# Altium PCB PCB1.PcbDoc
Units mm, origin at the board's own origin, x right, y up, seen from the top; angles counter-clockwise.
Board outline 64.13 x 24.77 mm, 2 copper layers (Top Layer, Bottom Layer); 42 components, 34 nets, 201 pads, 2 vias.
Unrouted connection lines stored in the file: 120.
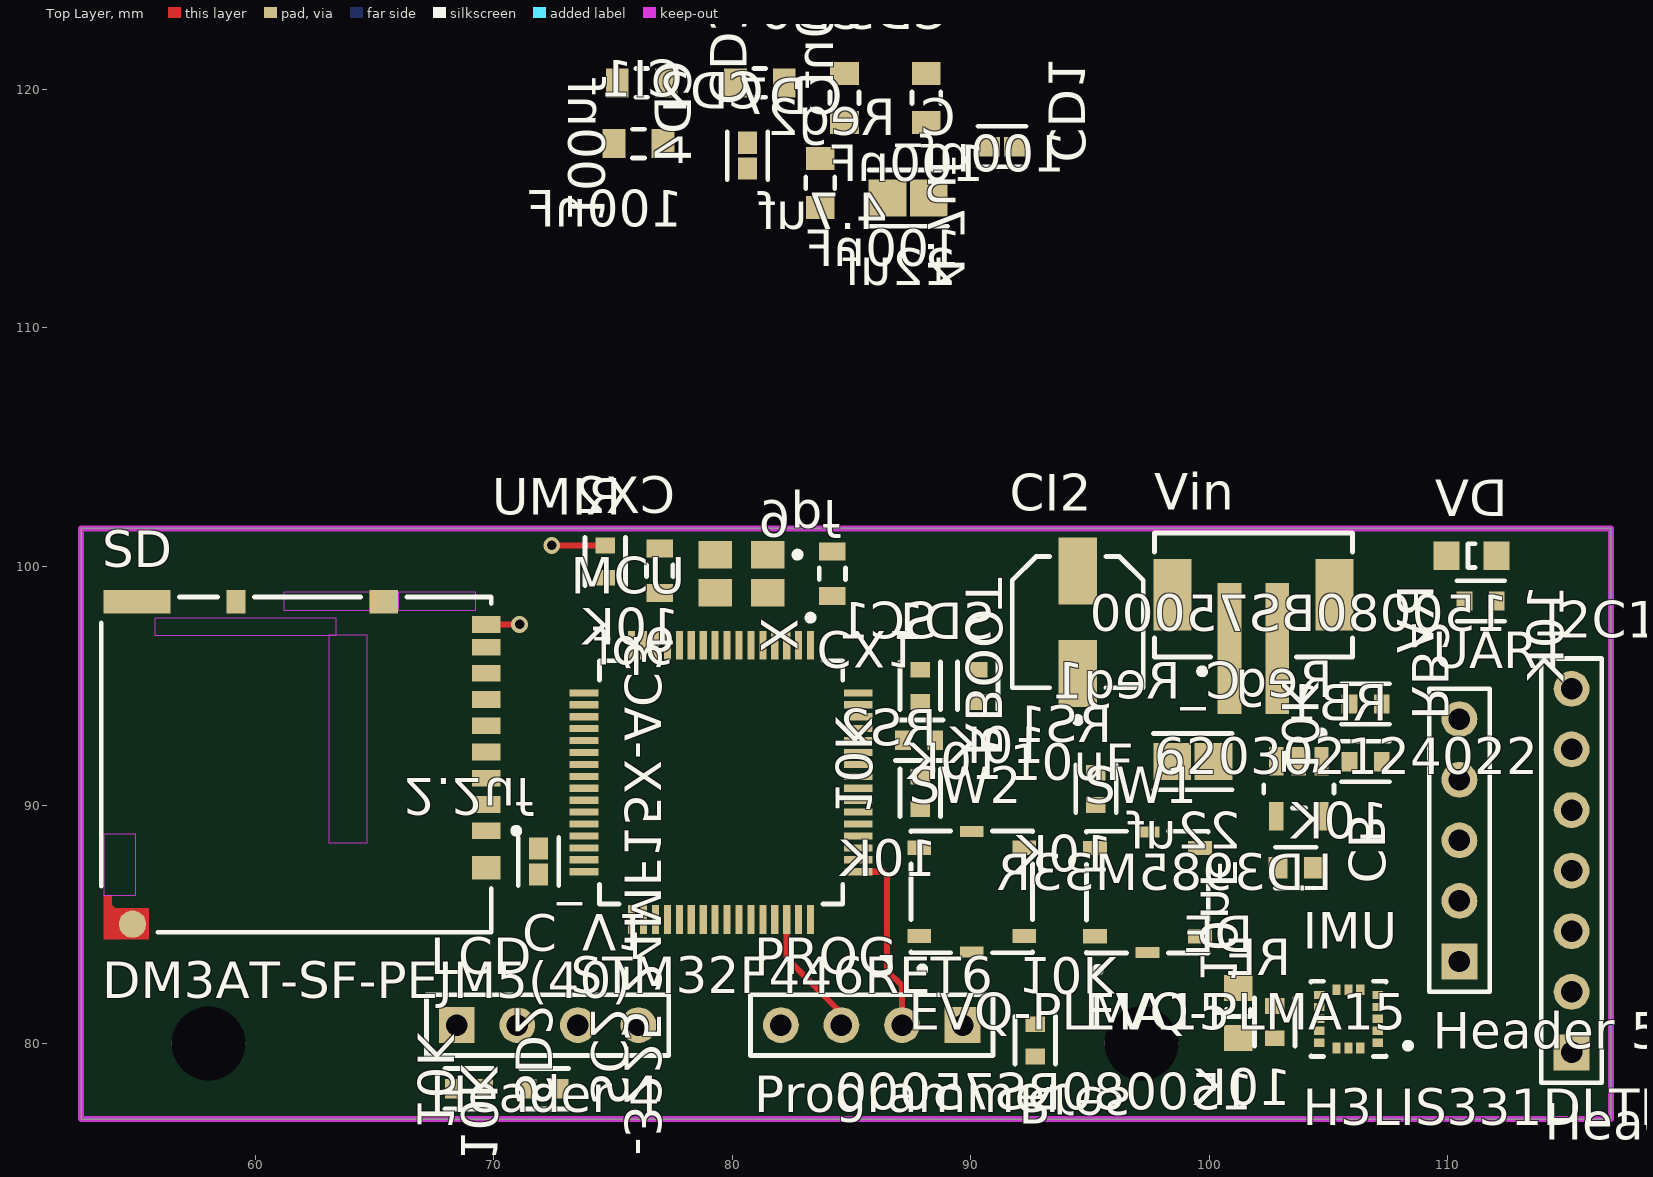
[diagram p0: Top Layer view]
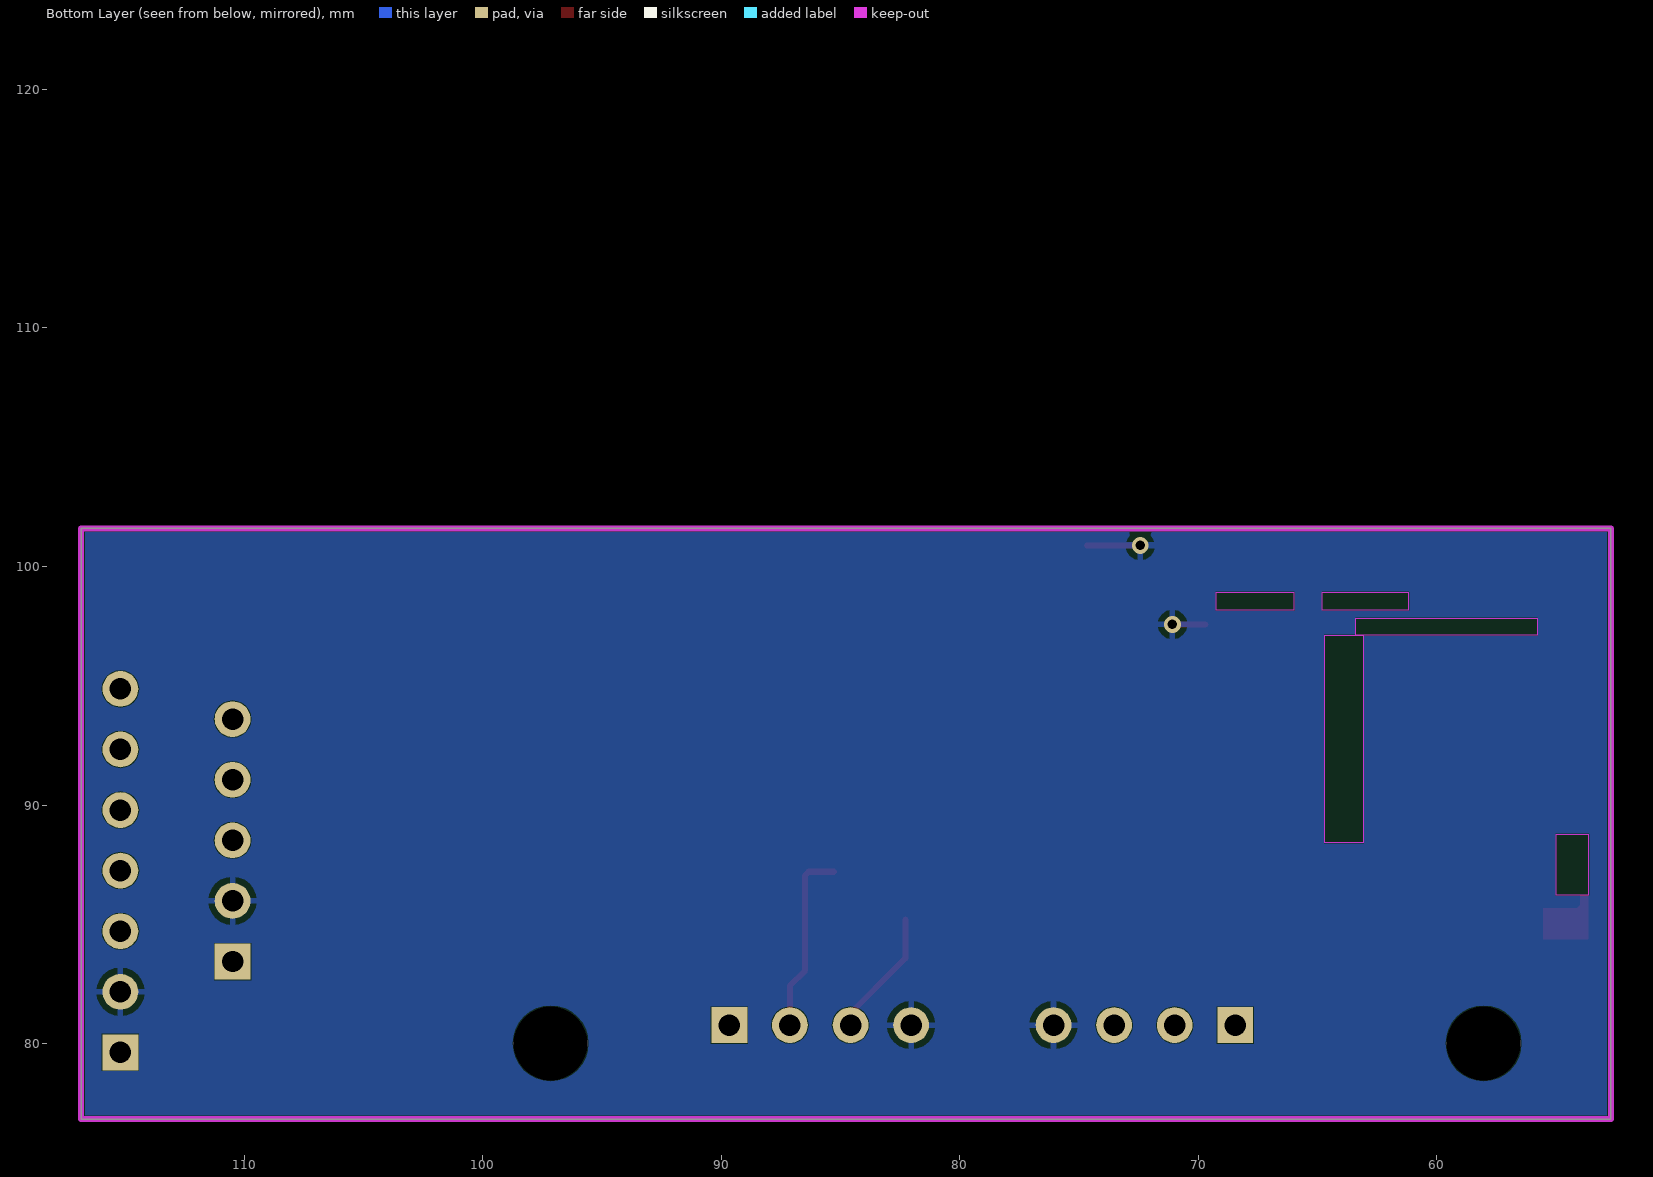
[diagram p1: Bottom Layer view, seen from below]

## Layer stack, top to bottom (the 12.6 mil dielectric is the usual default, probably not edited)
Top Solder: solder mask 0.0102, Solder Resist, Dk 3.5
Top Layer: signal copper 0.0356
Dielectric 1: dielectric 0.32, FR-4, Dk 4.8
Bottom Layer: signal copper 0.0356
Bottom Solder: solder mask 0.0102, Solder Resist, Dk 3.5

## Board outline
52.705,76.835 52.705,101.6 116.84,101.6 116.84,76.835

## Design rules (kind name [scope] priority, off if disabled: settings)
Clearance [All] p1: gap=0.025 ignorepadtopadclearanceinfootprint=FALSE
PolygonConnect [All] p1: connectstyle=Relief reliefconductorwidth=0.254 reliefentries=4 polygonreliefangle="90 Angle" airgapwidth=0.254
RoomDefinition Sheet1 [InComponentClass('Sheet1')] p1: confinementstyle=ConfineIn formatcopy=TRUE lockcomponents=FALSE outline 0,0 50.8,0 50.8,25.4 0,25.4
RoutingVias [All] p1: holewidth=0.711 width=1.27 viastyle="Through Hole" minholewidth=0.711 minwidth=1.27 maxholewidth=0.711 maxwidth=1.27
SolderMaskExpansion [All] p1: expansion=0.102 istentingtop=FALSE
Width [All] p1: maxlimit=0.5 minlimit=0.254 preferedwidth=0.254
30 further rules are at their usual default settings.

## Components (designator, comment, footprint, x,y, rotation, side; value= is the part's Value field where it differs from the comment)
C_Reg1 "22uf" FP-C2012-125-0_2-IPC_A 99.314,91.821 r0 top
C_Reg2 "22uf" FP-C2012-125-0_2-IPC_A 87.376,115.443 r0 top
C_V1 "2.2uf" FP-C1608-080-0_1-IPC_C 71.882,87.63 r270 top
CB "10nF" FP-CC0603-DA-MFG 103.632,87.376 r0 top value="10 nF"
CD1 "4.7uf" FP-C1608-080-0_1-IPC_C 91.313,117.602 r0 top
CD2 "4.7uf" FP-C1608-080-0_1-IPC_C 80.645,117.221 r90 top
CD3 "100nf" FP-CGA3E-0_3-0_1-IPC_A 76.209,120.269 r0 top
CD4 "100nf" FP-CGA3E-0_3-0_1-IPC_A 81.162,120.269 r180 top
CD5 "100nf" FP-CGA3E-0_3-0_1-IPC_A 88.138,119.643 r90 top
CD6 "100nF" FP-CGA3E-0_3-0_1-IPC_A 84.709,119.643 r90 top
CD7 "100nF" FP-CGA3E-0_3-0_1-IPC_A 83.693,116.078 r90 top
CI1 "100nF" FP-CGA3E-0_3-0_1-IPC_A 76.073,117.729 r0 top
CI2 "10uF" FP-SC-MFG 94.488,97.663 r90 top
CX1 "9pf" FP-CGA3E-0_3-0_1-IPC_B 84.201,99.695 r270 top
CX2 "9pf" FP-CGA3E-0_3-0_1-IPC_B 76.962,99.822 r90 top
DE "150080BS75000" 0805_A 101.219,81.28 r90 top
DV "150080BS75000" 0805_A 110.998,100.457 r0 top
I2C1 "Header 7" HDR1X7 115.189,79.629 r90 top
IMU "H3LIS331DLTR" FP-TFLGA16-7983231-MFG 105.836,81.034 r180 top
LCD "Header 4" HDR1X4 68.453,80.772 r0 top
MCU "STM32F446RET6" FP-LQFP64-5W-MFG 79.537,90.952 r270 top
PROG "Programmer" HDR1X4 89.662,80.772 r180 top
RB1 "10K" FP-RC0603-0_55-IPC_C 106.553,91.821 r180 top
RB2 "10K" FP-RC0603-0_55-IPC_C 106.553,94.234 r0 top
RBOOT "10K" FP-RC0603-0_55-IPC_C 87.842,92.71 r0 top
RE "10K" FP-RC0603-0_55-IPC_C 102.743,80.899 r90 top
Reg "LD3985M33R" FP-SOT23-5L-7049676-MFG 103.759,90.678 r270 top
RIMU "10K" FP-RC0603-0_55-IPC_C 74.676,100.203 r90 top
Rres "10K" FP-RC0603-0_55-IPC_C 92.71,80.137 r270 top
RS1 "10K" FP-RC0603-0_55-IPC_C 95.25,90.678 r90 top
RS2 "10K" FP-RC0603-0_55-IPC_C 87.884,90.509 r90 top
RV "10K" FP-RC0603-0_55-IPC_C 111.379,98.552 r0 top
SC1 "10K" FP-RC0603-0_55-IPC_C 87.884,94.996 r90 top
SC2 "10K" FP-RC0603-0_55-IPC_C 72.136,78.105 r0 top
SD "DM3AT-SF-PEJM5(40)" FP-DM3AT-SF-PEJM5_40-MFG 61.722,91.694 r270 top
SD1 "10K" FP-RC0603-0_55-IPC_C 90.297,94.996 r90 top
SD2 "10K" FP-RC0603-0_55-IPC_C 68.961,78.105 r0 top
SW1 "EVQ-PLMA15" FP-EVQ-PLMA15-MFG 97.409,86.345 r90 top
SW2 "EVQ-PLMA15" FP-EVQ-PLMA15-MFG 90.043,86.36 r90 top
UART "Header 5" HDR1X5 110.49,83.439 r90 top
Vin "620302124022" 620302124022 101.854,98.806 r180 top
X "TSX-3225 24MF15X-AC3" EPSON-TSX-3225_V 80.391,99.695 r180 top

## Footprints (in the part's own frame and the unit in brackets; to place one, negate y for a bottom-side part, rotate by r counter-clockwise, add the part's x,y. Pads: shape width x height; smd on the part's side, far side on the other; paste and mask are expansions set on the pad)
0805_A [mm] "Chip LED, 2-Leads, Body 2.0x1.3mm, IPC Medium Density"
  rect 1.1x1.2 smd: 1(-1.05,0) 2(1.05,0)
  silkscreen extent -0.15,-0.5 0.15,0.5, body extent -1,-0.63 1,0.63, height 0.68
620302124022 [mm] "2.00mm SMT Male Vertical Shrouded Header, 2p"
  rect 1x5.5 smd: 1(1,2.25) 2(-1,2.25)
  rect 1.6x3 smd: MP1(-3.4,0) MP2(3.4,0)
  silkscreen extent -4.15,-2.6 4.15,3.32, body extent -4,-2.5 4,4.51, height 6.77
EPSON-TSX-3225_V [mm] "SMD, 4-Leads, Body 3.2x2.5mm"
  rect 1.4x1.15 smd: 1(-1.1,-0.8) 2(1.1,-0.8) 3(1.1,0.8) 4(-1.1,0.8)
  silkscreen extent -2.48,-0.92 -2.23,-0.68, body extent -1.6,-1.25 1.6,1.25, height 0.6
FP-C1608-080-0_1-IPC_C [mm]
  rect 0.931x0.812 smd paste+0 mask+0: 1(-0.541,0) 2(0.541,0)
  silkscreen extent -1.01,-0.85 1.01,0.85, body extent -0.8,-0.4 0.8,0.4, height 0.9
FP-C2012-125-0_2-IPC_A [mm]
  rect 1.578x1.556 smd paste+0 mask+0: 1(-0.864,0) 2(0.864,0)
  silkscreen extent -1.65,-1.18 1.65,1.18, body extent -1,-0.63 1,0.63, height 1.45
FP-CC0603-DA-MFG [mm]
  rect 0.8x0.9 smd paste+0 mask+0: 1(-0.75,0) 2(0.75,0)
  silkscreen extent -0.85,-0.85 0.85,0.85, body extent -0.8,-0.4 0.8,0.4, height 0.9
FP-CGA3E-0_3-0_1-IPC_A [mm]
  rect 0.956x1.206 smd paste+0 mask+0: 1(-1.025,0) 2(1.025,0)
  silkscreen extent -0.25,-0.6 0.25,0.6, body extent -0.8,-0.4 0.8,0.4, height 1.1
FP-CGA3E-0_3-0_1-IPC_B [mm]
  rect 0.756x1.106 smd paste+0 mask+0: 1(-0.925,0) 2(0.925,0)
  silkscreen extent -0.25,-0.55 0.25,0.55, body extent -0.8,-0.4 0.8,0.4, height 1.1
FP-DM3AT-SF-PEJM5_40-MFG [mm]
  rect 0.7x1.2 smd paste+0 mask+0: 1(2.775,7.975) 2(1.675,7.975) 3(0.575,7.975) 4(-0.525,7.975) 5(-1.625,7.975) 6(-2.725,7.975) 7(-3.825,7.975) 8(-4.925,7.975) 9(-5.875,7.975)
  rect 1x0.8 smd paste+0 mask+0: 10(-6.825,-2.525)
  rect 1x1.2 smd paste+0 mask+0: 11(4.325,7.975) 12(-6.825,3.675)
  rect 1x2.8 smd paste+0 mask+0: 13(-6.825,-6.675)
  round 1.145 smd paste+0 mask+0: 14(6.689,-6.861)
  Top Layer region: 6.025,-6.175 7.325,-6.175 7.325,-8.075 5.475,-8.075 5.475,-7.725 5.875,-7.725 6.025,-7.575 6.025,-6.175
  Keep-Out Layer region: 2.925,-8.075 5.475,-8.075 5.475,-6.725 2.925,-6.725
  Keep-Out Layer region: -5.425,1.375 3.275,1.375 3.275,2.975 -5.425,2.975
  Keep-Out Layer region: -6.125,-5.925 -5.425,-5.925 -5.425,1.675 -6.125,1.675
  Keep-Out Layer region: -7.225,-0.525 -6.475,-0.525 -6.475,3.075 -7.225,3.075
  Keep-Out Layer region: -7.225,4.275 -6.475,4.275 -6.475,7.525 -7.225,7.525
  silkscreen extent -7.02,-8.17 7.02,9.35, body extent -6.93,-7.95 6.92,8.2, height 1.68
FP-EVQ-PLMA15-MFG [mm]
  rect 0.45x1 smd paste+0 mask+0: 1(-2.525,0) 2(2.525,0)
  rect 0.6x1 smd paste+0 mask+0: A(-1.85,2.2) A'(-1.85,-2.2) B(1.85,2.2) B'(1.85,-2.2)
  silkscreen extent -3.37,-2.55 2.55,2.55, body extent -2.85,-2.8 2.85,2.8, height 0.25
FP-LQFP64-5W-MFG [mm]
  rect 1.2x0.3 smd paste+0 mask+0: 1(-5.75,3.75) 2(-5.75,3.25) 3(-5.75,2.75) 4(-5.75,2.25) 5(-5.75,1.75) 6(-5.75,1.25) 7(-5.75,0.75) 8(-5.75,0.25) 9(-5.75,-0.25) 10(-5.75,-0.75) 11(-5.75,-1.25) 12(-5.75,-1.75) 13(-5.75,-2.25) 14(-5.75,-2.75) 15(-5.75,-3.25) 16(-5.75,-3.75) 33(5.75,-3.75) 34(5.75,-3.25) 35(5.75,-2.75) 36(5.75,-2.25) 37(5.75,-1.75) 38(5.75,-1.25) 39(5.75,-0.75) 40(5.75,-0.25) 41(5.75,0.25) 42(5.75,0.75) 43(5.75,1.25) 44(5.75,1.75) 45(5.75,2.25) 46(5.75,2.75) 47(5.75,3.25) 48(5.75,3.75)
  rect 0.3x1.2 smd paste+0 mask+0: 17(-3.75,-5.75) 18(-3.25,-5.75) 19(-2.75,-5.75) 20(-2.25,-5.75) 21(-1.75,-5.75) 22(-1.25,-5.75) 23(-0.75,-5.75) 24(-0.25,-5.75) 25(0.25,-5.75) 26(0.75,-5.75) 27(1.25,-5.75) 28(1.75,-5.75) 29(2.25,-5.75) 30(2.75,-5.75) 31(3.25,-5.75) 32(3.75,-5.75) 49(3.75,5.75) 50(3.25,5.75) 51(2.75,5.75) 52(2.25,5.75) 53(1.75,5.75) 54(1.25,5.75) 55(0.75,5.75) 56(0.25,5.75) 57(-0.25,5.75) 58(-0.75,5.75) 59(-1.25,5.75) 60(-1.75,5.75) 61(-2.25,5.75) 62(-2.75,5.75) 63(-3.25,5.75) 64(-3.75,5.75)
  silkscreen extent -7.02,-5.1 5.1,5.1
FP-RC0603-0_55-IPC_C [mm]
  rect 0.659x0.812 smd paste+0 mask+0: 1(-0.677,0) 2(0.677,0)
  silkscreen extent -1.01,-0.85 1.01,0.85, body extent -0.8,-0.4 0.8,0.4, height 0.55
FP-SC-MFG [mm]
  rect 2.8x1.6 smd paste+0 mask+0: 1(-2.15,0) 2(2.15,0)
  silkscreen extent -4.22,-2.75 2.75,2.75, body extent -3.8,-3 3.8,3, height 0.25
FP-SOT23-5L-7049676-MFG [mm]
  rect 1.2x0.6 smd paste+0 mask+0: 1(-1.15,0.95) 2(-1.15,0) 3(-1.15,-0.95) 4(1.15,-0.95) 5(1.15,0.95)
  silkscreen extent -2.45,-1.47 0.8,1.47, body extent -0.87,-1.5 0.88,1.5, height 1.45
FP-TFLGA16-7983231-MFG [mm]
  rect 0.45x0.35 smd paste+0 mask+0: 1(-1.225,1) 2(-1.225,0.5) 3(-1.225,0) 4(-1.225,-0.5) 5(-1.225,-1) 9(1.225,-1) 10(1.225,-0.5) 11(1.225,0) 12(1.225,0.5) 13(1.225,1)
  rect 0.35x0.45 smd paste+0 mask+0: 6(-0.5,-1.225) 7(0,-1.225) 8(0.5,-1.225) 14(0.5,1.225) 15(0,1.225) 16(-0.5,1.225)
  silkscreen extent -2.63,-1.57 1.57,1.57, body extent -1.5,-1.5 1.5,1.5, height 1
HDR1X4 [mm] "Connector; Header; 4 Position"
  rect 1.5x1.5 hole 0.9: 1(0,0)
  round 1.5 hole 0.9: 2(2.54,0) 3(5.08,0) 4(7.62,0)
  silkscreen extent -1.27,-1.27 8.89,1.27
HDR1X5 [mm] "Connector; Header; 5 Position"
  rect 1.5x1.5 hole 0.9: 1(0,0)
  round 1.5 hole 0.9: 2(2.54,0) 3(5.08,0) 4(7.62,0) 5(10.16,0)
  silkscreen extent -1.27,-1.27 11.43,1.27
HDR1X7 [mm] "Connector; Header; 7 Position"
  rect 1.5x1.5 hole 0.9: 1(0,0)
  round 1.5 hole 0.9: 2(2.54,0) 3(5.08,0) 4(7.62,0) 5(10.16,0) 6(12.7,0) 7(15.24,0)
  silkscreen extent -1.27,-1.27 16.51,1.27

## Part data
C_Reg1 C_Reg2: library part CMP-08246-007072-1, "Multilayer Ceramic Capacitors 22μF ±20% 16V X6S SMD 0805", Capacitance=22uF, Case Code (Imperial)=0805, Case Code (Metric)=2012, Dielectric=X6S, Dielectric Material=Ceramic, Max Operating Temperature=105°C, Min Operating Temperature=-55°C, Package Quantity=2000, Tolerance=20%, Voltage Rating=16V
C_V1 CD1 CD2: library part CMP-2000-04981-2, "Multilayer Ceramic Capacitors 4.7μF ±10% 16V X5R SMD 0603", Capacitance=4.7uF, Case Code (Imperial)=0603, Case Code (Metric)=1608, Dielectric=X5R, Dielectric Material=Ceramic, Max Operating Temperature=85°C, Min Operating Temperature=-55°C, Package Quantity=1, Tolerance=10%, Voltage=16V
CB: library part CMP-2100-03600-2, "CAP CER 10000PF 50V X7R 0603", Capacitance="10 nF", Manufacturer=YAGEO, Manufacturer Part Number=CC0603KRX7R9BB103, Package=CC0603-DA, Temperature="-55°C to +125°C", Temperature Characteristic=X7R, Temperature Coefficient=15%, Temperature Range High=+125°C, Temperature Range Low=-55°C, Tolerance=0.1, Voltage="50 V"
CD3 CD4 CD5: library part CMP-2000-07546-2, "Cap Ceramic 100nF 50V X7R 10% Pad SMD 0603 +125°C Automotive T/R", Capacitance=100nF, Case Code (Imperial)=0603, Case Code (Metric)=1608, Dielectric=X7R, Max Operating Temperature=125°C, Min Operating Temperature=-55°C, Package Quantity=1, Ratings=AEC-Q200, Tolerance=10%, Voltage=50V
CD6 CD7 CI1: library part CMP-2000-07546-2, "Cap Ceramic 100nF 50V X7R 10% Pad SMD 0603 +125°C Automotive T/R", Case Code (Imperial)=0603, Case Code (Metric)=1608, Dielectric=X7R, Max Operating Temperature=125°C, Min Operating Temperature=-55°C, Package Quantity=1, Ratings=AEC-Q200, Tolerance=10%, Voltage=50V
CI2: library part CMP-05427-000087-1, "CAP ALUM 10UF 20% 35V SMD", Case/Package=Radial, Leakage Current=3uA, Max Operating Temperature=85°C, Min Operating Temperature=-40°C, Package Quantity=1, Ripple Current=30mA, Tolerance=20%, Voltage=35V
CX1 CX2: library part CMP-08246-000963-1, "Cap Ceramic 9pF 50V C0G 0.5pF Pad SMD 0603 +125°C Automotive T/R", Capacitance=9pF, Case Code (Imperial)=0603, Case Code (Metric)=1608, Dielectric=C0G, Max Operating Temperature=125°C, Min Operating Temperature=-55°C, Package Quantity=4000, Ratings=AEC-Q200, Voltage Rating=50V
DE DV: library part CMP-1426-00008-1, "SMD mono-color Chip LED, WL-SMCW, Blue", Color=Blue, Manufacturer="Wuerth Elektronik"
I2C1: "Header, 7-Pin"
IMU: library part CMP-12175-000002-1, "ACCEL 100-400G I2C/SPI 16TFLGA", Manufacturer=STMicroelectronics, Max Supply Voltage=3.6V, Min Supply Voltage=2.16V, Operating Supply Current=10-300uA, Package=TFLGA16-7983231, Temperature="-40°C to +85°C", Temperature Range High=+85°C, Temperature Range Low=-40°C
LCD: "Header, 4-Pin"
MCU: library part CMP-12105-000007-1, "IC MCU 32BIT 512KB FLASH 64LQFP", Ambient Temperature Range High=+85°C, Ambient Temperature Range Low=-40°C, Frequency=180MHz, Manufacturer=ST, Max Junction Temp=+105°C, Max Supply Voltage=3.6V, Min Supply Voltage=1.7V, Package=LQFP64-5W, Temperature="-40°C to +105°C"
PROG: library part "Header 4", "Header, 4-Pin"
RB1 RB2 RBOOT RE RIMU Rres RS1 RS2 RV SC1 SC2 SD1 SD2: library part CMP-2100-03664-2, "RES 10K OHM 1% 1/10W 0603", Case Code (Imperial)=0603, Case Code (Metric)=1608, Max Operating Temperature=155°C, Max Power Dissipation=100mW, Min Operating Temperature=-55°C, Resistance=10kR, Resistance Tolerance=1%, Resistor Type="Thick Film", Temperature Coefficient=100ppm/°C, Voltage Rating=75V, Voltage Rating (DC)=50V
Reg: library part CMP-0244-00328-2, "IC REG LINEAR 3.3V 150MA SOT23-5", Case/Package=SOT-23, Dropout Voltage=60mV, Input Bias Current=85uA, Max Input Voltage=6V, Max Operating Temperature=125°C, Max Output Current=150mA, Min Current Limit=300mA, Min Input Voltage=2.5V, Min Operating Temperature=-40°C, Min Output Voltage=3.3V, Output Voltage Accuracy=2%, Package Quantity=1, Quiescent Current=150uA
SD: library part CMP-11597-000006-1, "CONN MICRO SD R/A PUSH-PUSH SMD", Color=Black, Contact Resistance=100mR, Current Rating=500mA, Flammability Rating="UL94 V-0", Insulation Resistance=1GR, Max Operating Temperature=85°C, Max Voltage Rating (AC)=125V, Min Operating Temperature=-25°C, Package Quantity=400
SW1 SW2: library part CMP-05618-000006-1, "SWITCH TACTILE SPST-NO 0.02A 15V", Contact Current Rating=20mA, Contact Resistance=50mΩ, Manufacturer="Panasonic Electronic Components", Operating Force=2.6N, Package=0, Temperature="-20°C to +70°C", Temperature Range High=+70°C, Temperature Range Low=-20°C, Voltage Rating Dc=15V
UART: "Header, 5-Pin"
Vin: library part CMP-1502-00660-1, "Male Shrouded Header WR-WTB, SMT, Vertical, pitch 2 mm, 1 x 2 position", Contact Resistance=20mOhm, Manufacturer="Wurth Elektronik", Operating Temperature=-25to85degC, Working Voltage=100VAC
X: library part CMP-2000-07333-1, "MHz Range Crystal, 24 MHz, -40 to 85 degC, 4-Pin SMD, RoHS, Tape and Reel", Frequency=24MHz, Frequency Stability=10PPM, Load Capacitance=9pF, Manufacturer=Epson, Operating Temperature Range=-40Cto+85C, Package / Case=3.2mmx2.5mm, Package Description="4-Pin Surface Mount Device, Body 3.2 x 2.5 mm", Package Reference=TSX-3225

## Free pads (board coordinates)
  oval 3.1x1.524 hole 3.1: 1(58.039,80.01) 1(97.155,80.01)

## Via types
v1: diameter 0.7, hole 0.4, Top Layer to Bottom Layer, 2 vias

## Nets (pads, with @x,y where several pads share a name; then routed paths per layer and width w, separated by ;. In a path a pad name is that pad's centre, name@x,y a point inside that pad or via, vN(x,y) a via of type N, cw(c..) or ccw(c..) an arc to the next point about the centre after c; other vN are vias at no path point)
+3V3: C_Reg2.2 CD1.1 CD2.1 CD3.1 CD4.1 CD5.1 CD6.1 CD7.1 CI1.2 CI2.2 DV.2 I2C1.1 IMU.1 IMU.14 IMU.15 LCD.3 MCU.1 MCU.13 MCU.19 MCU.32 MCU.48 MCU.64 Reg.5 Rres.2 SC1.2 SC2.2 SD1.2 SD2.2 SD.4 SW1.A SW1.A' SW2.A SW2.A' UART.1
ADC0: MCU.15 RB1.1 RB2.2
GND: C_Reg1.1 C_Reg2.1 C_V1.2 CB.2 CD1.2 CD2.2 CD3.2 CD4.2 CD5.2 CD6.2 CD7.2 CI1.1 CI2.1 CX1.2 CX2.2 I2C1.2 IMU.5 IMU.8 IMU.10 IMU.12 IMU.13 IMU.16 LCD.4 MCU.12 MCU.18 MCU.31 MCU.47 MCU.63 PROG.4 RBOOT.2 RE.2 Reg.2 RIMU.2 RS1.2 RS2.2 RV.2 SD.2 SD.6 SD.9 SD.10 SD.11 SD.12 SD.13 SD.14 UART.2 Vin.1 X.2 X.4 | length 3.6
  Top Layer w0.254: SD.9 v1(71.087,97.569) ; v1(72.432,100.88) RIMU.2
INDICATOR: DE.2 MCU.11
"INT 1": IMU.11 MCU.26
"INT 2": IMU.9 MCU.27
"INT 3": I2C1.5 MCU.28 UART.5
"INT 4": I2C1.6 MCU.55
"INT 5": I2C1.7 MCU.56
M_boot: MCU.60 RBOOT.1
M_C_V: C_V1.1 MCU.30
M_X1: CX1.1 MCU.5 X.1
M_X2: CX2.1 MCU.6 X.3
MISO: MCU.22 SD.7
MOSI: MCU.23 SD.3
NetCB_1: CB.1 Reg.4
NetDE_1: DE.1 RE.1
NetDV_1: DV.1 RV.1
NRST: MCU.7 PROG.1 Rres.1
RX: MCU.43 UART.3
S1: RS1.1 SW1.B SW1.B'
S2: RS2.1 SW2.B SW2.B'
SA_IMU: IMU.7 MCU.8 RIMU.1
SCK: MCU.21 SD.5
SCL1: I2C1.3 MCU.58 SC1.1
SCL2: LCD.2 MCU.29 SC2.1
SCL3: IMU.4 MCU.41
SDA1: I2C1.4 MCU.59 SD1.1
SDA2: LCD.1 MCU.53 SD2.1
SDA3: IMU.6 MCU.40
SWCLK: MCU.49 PROG.2 | length 7.8
  Top Layer w0.254: MCU.49 86.338,87.202 86.487,87.053 86.487,83.058 87.122,82.423 PROG.2
SWDIO: MCU.46 PROG.3 | length 5.2
  Top Layer w0.254: MCU.46 82.287,83.575 PROG.3@84.814,81.048
TX: MCU.42 UART.4
Vin: C_Reg1.2 RB2.1 Reg.1 Reg.3 Vin.2
pads on no net: IMU.2 IMU.3 MCU.2 MCU.3 MCU.4 MCU.9 MCU.10 MCU.14 MCU.16 MCU.17 MCU.20 MCU.24 MCU.25 MCU.33 MCU.34 MCU.35 MCU.36 MCU.37 MCU.38 MCU.39 MCU.44 MCU.45 MCU.50 MCU.51 MCU.52 MCU.54 MCU.57 MCU.61 MCU.62 RB1.2 SD.1 SD.8 SW1.1 SW1.2 SW2.1 SW2.2 Vin.MP1 Vin.MP2

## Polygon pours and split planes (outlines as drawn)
GND on Bottom Layer "GND_L02_P000" (solid, remove dead copper, pour order 0): 50.927,102.87 51.054,102.997 119.888,102.997 119.888,74.676 121.158,73.406 120.65,72.898 50.165,72.898

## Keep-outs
Keep-Out Layer:
  lines w0.254: 52.705,76.835 52.705,101.6 116.84,101.6 116.84,97.409 116.84,76.835 109.093,76.835 52.705,76.835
